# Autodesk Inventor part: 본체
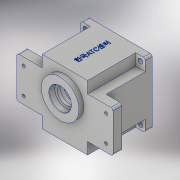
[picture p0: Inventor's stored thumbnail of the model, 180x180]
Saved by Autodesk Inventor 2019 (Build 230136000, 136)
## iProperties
Created: 2020-07
Part Number: 본체
Material: 알루미늄 6061
Document SubType Name: Modeling
Designer: Admin
Density: 2.7 g/cm^3
Appearance: 알루미늄 - 평지
Mass: 876.465 g
Surface Area: 793.597 cm^2
Volume: 324.617 cm^3
Author: Admin
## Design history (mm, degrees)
sketch "스케치1"
  geometry: L1 (-70, -30)-(70, -30); L2 (70, -30)-(70, 30); L3 (70, 30)-(-70, 30); L4 (-70, 30)-(-70, -30); L5 (-70, -30)-(70, 30); L6 (70, -30)-(-70, 30); 1 further point
  constraints: 12 end point, 2 midpoint, 2 parallel, 1 horizontal, 1 perpendicular
  dimensions: "d0" = 60 distance of L1.end L2.end; "d1" = 140 distance of L2.end L3.end
extrude "돌출1" new body sketch "스케치1" distance "d2" = 13; taper "d3" = 0 deg
sketch "스케치2"
  geometry: L1 (-47, -47)-(47, -47); L2 (47, -47)-(47, 47); L3 (47, 47)-(-47, 47); L4 (-47, 47)-(-47, -47); L5 (-47, -47)-(47, 47); L6 (47, -47)-(-47, 47); 1 further point
  constraints: 12 end point, 2 midpoint, 2 parallel, 1 horizontal, 1 perpendicular
  dimensions: "d4" = 94 distance of L2.end L3.end; "d5" = 94 distance of L1.end L2.end
extrude "돌출2" join sketch "스케치2" distance "d6" = 80; taper "d7" = 0 deg
sketch "스케치3"
  geometry: C1 r 27.5 at (0, 11); 1 further point
  constraints: 1 centre point
  dimensions: "d8" = 55 diameter of C1; "d9" = 11 distance of C1.centre point (0, 0)
extrude "돌출3" join sketch "스케치3" distance "d10" = 7; taper "d11" = 0 deg
sketch "스케치4"
  geometry: L1 (-33, -30)-(33, -30); L2 (33, -30)-(33, 30); L3 (33, 30)-(-33, 30); L4 (-33, 30)-(-33, -30); L5 (-33, -30)-(33, 30); L6 (33, -30)-(-33, 30); L7 (-47, 47)-(-47, 30) reference; L8 (-33, 30)-(-47, 30); L9 (-47, 30)-(-47, 47); L10 (-47, 47)-(-33, 47); L11 (-33, 47)-(-33, 30); L12 (47, 47)-(-47, 47) reference; L13 (33, 30)-(47, 30); L14 (47, 30)-(47, 47); L15 (47, 47)-(33, 47); L16 (33, 47)-(33, 30); L17 (-47, -47)-(47, -47) reference; L18 (33, -30)-(47, -30); L19 (47, -30)-(47, -47); L20 (47, -47)-(33, -47); L21 (33, -47)-(33, -30); L22 (-33, -30)-(-47, -30); L23 (-47, -30)-(-47, -47); L24 (-47, -47)-(-33, -47); L25 (-33, -47)-(-33, -30); 1 further point
  constraints: 44 end point, 10 parallel, 5 horizontal, 5 perpendicular, 2 midpoint
  dimensions: "d12" = 66 distance of L2.end L3.end; "d13" = 60 distance of L1.end L2.end
extrude "돌출4" cut sketch "스케치4" distance "d14" = 70; taper "d15" = 0 deg
sketch "스케치5"
  geometry: C1 r 27.5 at (0, 0) reference; C2 r 16 at (0, 0); 1 further point
  constraints: 1 centre point, 1 coincident
  dimensions: "d16" = 32 diameter of C2
extrude "돌출5" cut sketch "스케치5" distance "d17" = 8.3; taper "d18" = 0 deg
sketch "스케치6"
  geometry: L1 (-5, -1.3)-(27, -1.3) reference; L2 (-5, 7)-(27, 7) reference; L3 (38.5, 7)-(-16.5, 7) reference; L4 (11, 7)-(11, 6.2); L5 (11, 6.2)-(27, 6.2); L6 (27, 7)-(27, -1.3) reference; L7 (27, 6.2)-(27.462, 7); L8 (27.462, 7)-(11, 7); 1 further point
  constraints: 8 end point, 2 point on line, 1 collinear, 1 horizontal, 1 midpoint, 1 vertical
  dimensions: "d23" = 0.8 distance of L4.start L4.end; "d24" = 30 deg angle of L6 L7
revolve "회전1" sketch "스케치6" stored, may be unused: angle "d25" = 90 deg
sketch "스케치7"
  geometry: L1 (-60, -19)-(60, -19); L2 (60, -19)-(60, 19); L3 (60, 19)-(-60, 19); L4 (-60, 19)-(-60, -19); L5 (-60, -19)-(60, 19); L6 (60, -19)-(-60, 19); C1 r 2.25 at (-60, 19); C2 r 2.25 at (-60, -19); C3 r 2.25 at (60, -19); C4 r 2.25 at (60, 19); 1 further point
  constraints: 12 end point, 4 centre point, 4 coincident, 2 midpoint, 2 parallel, 1 horizontal, 1 perpendicular
  dimensions: "d26" = 38 distance of L1.end L2.end; "d27" = 120 distance of L1.start L1.end; "d28" = 4.5 diameter of C2; "d29" = 4.5 diameter of C1; "d30" = 4.5 diameter of C4; "d31" = 4.5 diameter of C3
extrude "돌출6" cut sketch "스케치7" stored distance "d32" = 0; taper "d33" = 0 deg
sketch "스케치8"
  geometry: C1 r 2.25 at (-60, 19) reference; C2 r 5 at (-60, 19); C3 r 2.25 at (-60, -19) reference; C4 r 5 at (-60, -19); C5 r 2.25 at (60, -19) reference; C6 r 5 at (60, -19); C7 r 2.25 at (60, 19) reference; C8 r 5 at (60, 19); 1 further point
  constraints: 4 centre point, 4 coincident
  dimensions: "d34" = 10 diameter of C2; "d35" = 10 diameter of C4; "d36" = 10 diameter of C6; "d37" = 10 diameter of C8
extrude "돌출7" cut sketch "스케치8" distance "d38" = 5; taper "d39" = 0 deg
fillet "모깎기1" dims "d40" = 3
fillet "모깎기2" dims "d41" = 3
sketch "스케치9"
  geometry: L1 (-40, -40)-(40, -40); L2 (40, -40)-(40, 40); L3 (40, 40)-(-40, 40); L4 (-40, 40)-(-40, -40); L5 (-40, -40)-(40, 40); L6 (40, -40)-(-40, 40); C1 r 3.5 at (-40, 40); C2 r 3.5 at (-40, -40); C3 r 3.5 at (40, -40); C4 r 3.5 at (40, 40); 1 further point
  constraints: 12 end point, 4 centre point, 4 coincident, 2 midpoint, 2 parallel, 1 horizontal, 1 perpendicular
  dimensions: "d42" = 80 distance of L2.end L3.end; "d43" = 80 distance of L1.end L2.end; "d44" = 7 diameter of C4; "d45" = 7 diameter of C3; "d46" = 7 diameter of C2; "d47" = 7 diameter of C1
extrude "돌출8" cut sketch "스케치9" stored distance "d48" = 5; taper "d49" = 0 deg
sketch "스케치10"
  geometry: C1 r 43 at (0, 0); 1 further point
  constraints: 1 centre point, 1 coincident
  dimensions: "d50" = 86 diameter of C1
extrude "돌출9" cut sketch "스케치10" distance "d51" = 9; taper "d52" = 0 deg
sketch "스케치11"
  geometry: A1 r 36 centre (0, 0) between (-36, 0) and (36, 0); A2 r 4 centre (-36, 0) between (-36.19, -3.995) and (-36.19, 3.995); A3 r 4 centre (36, 0) between (36.19, 3.995) and (36.19, -3.995); A4 r 3 centre (-36.333, -6.992) between (-35.772, -4.045) and (-39.279, -7.559); A5 r 3 centre (-36.333, 6.992) between (-39.279, 7.559) and (-35.772, 4.045); A6 r 3 centre (36.333, -6.992) between (39.279, -7.559) and (35.772, -4.045); A7 r 3 centre (36.333, 6.992) between (35.772, 4.045) and (39.279, 7.559); A8 r 40 centre (0, 0) between (-39.279, -7.559) and (39.279, -7.559); A9 r 40 centre (0, 0) between (39.279, 7.559) and (-39.279, 7.559); 1 further point
  constraints: 26 point on circle, 9 centre point, 4 tangent, 2 coincident
  dimensions: "d54" = 72 diameter of A1; "d55" = 8 diameter of A2; "d56" = 8 diameter of A3; "d57" = 6 diameter of A5; "d58" = 6 diameter of A4; "d59" = 6 diameter of A6; "d60" = 6 diameter of A7
extrude "돌출10" cut sketch "스케치11" distance "d61" = 62; taper "d62" = 0 deg
sketch "스케치12"
  geometry: A1 r 21 centre (0, 11) between (12.163, -6.119) and (-12.163, -6.119); A2 r 15 centre (0, -20) between (-11.584, -10.47) and (11.584, -10.47); A3 r 3 centre (-13.901, -8.565) between (-11.584, -10.47) and (-12.163, -6.119); A4 r 3 centre (13.901, -8.565) between (12.163, -6.119) and (11.584, -10.47); 1 further point
  constraints: 8 point on circle, 4 centre point, 4 tangent, 2 vertical alignment
  dimensions: "d63" = 42 diameter of A1; "d64" = 30 diameter of A2; "d65" = 11 distance of point (0, 0) A1.centre; "d66" = 20 distance of A2.centre point (0, 0); "d67" = 6 diameter of A3; "d68" = 6 diameter of A4
extrude "돌출11" join sketch "스케치12" distance "d69" = 7; taper "d70" = 0 deg
sketch "스케치13"
  geometry: C1 r 17.5 at (0, 11); 2 further points
  constraints: 1 centre point, 1 coincident
  dimensions: "d71" = 35 diameter of C1
extrude "돌출12" cut sketch "스케치13" distance "d72" = 10; taper "d73" = 0 deg
chamfer "모따기1" distance "d74" = 1; stored, may be unused: second distance "d75" = 2, angle "d76" = 45 deg
sketch "스케치14"
  geometry: C1 r 11 at (0, -20); A1 r 15 centre (0, -20) between (-11.584, -10.47) and (11.584, -10.47) reference; 1 further point
  constraints: 1 centre point, 1 coincident
  dimensions: "d77" = 22 diameter of C1
extrude "돌출13" cut sketch "스케치14" distance "d78" = 7; taper "d79" = 0 deg
sketch "스케치15"
  geometry: C1 r 27.5 at (0, 0) reference; C2 r 12.5 at (0, 0); 1 further point
  constraints: 1 centre point, 1 coincident
  dimensions: "d80" = 25 diameter of C2
extrude "돌출14" cut sketch "스케치15" stored distance "d81" = 0; taper "d82" = 0 deg
sketch "스케치16"
  geometry: C1 r 11 at (0, 0) reference; C2 r 9.5 at (0, 0); 1 further point
  constraints: 1 centre point, 1 coincident
  dimensions: "d83" = 19 diameter of C2
extrude "돌출15" cut sketch "스케치16" distance "d84" = 3; taper "d85" = 0 deg
chamfer "모따기2" distance "d86" = 1; stored, may be unused: second distance "d87" = 2, angle "d88" = 45 deg
sketch "스케치17"
  geometry: A1 r 4 centre (-36, 0) between (-36.19, -3.995) and (-36.19, 3.995) reference; A2 r 4 centre (36, 0) between (36.19, 3.995) and (36.19, -3.995) reference; 3 further points
  constraints: 2 coincident
hole "구멍1" sketch "스케치17" at (-36, 0), (36, 0) diameter "d89" = 3.242; stored, may be unused: countersink angle "d93" = 90 deg, drill point angle "d95" = 118 deg; dims "d90" = 7, "d91" = 4, "d92" = 2, "d94" = 9
sketch "스케치18"
  geometry: L1 (66, 0)-(0, 0) reference; L2 (-11, 80)-(77, 80) reference; 3 further points
  constraints: 1 midpoint, 1 vertical alignment, 1 other
  dimensions: "d96" = 40 distance from line of L2 point (33, 40)
feature "엠보싱1" sketch "스케치18" dims "d0" = 60, "d1" = 140, "d97" = 0.5, "d98" = 0
fillet "모깎기3" dims "d99" = 3
node "솔리드1"
node "투영된 루프1"
other parameters: "d19" = 0.5, "d20" = 2, "d21" = 0
